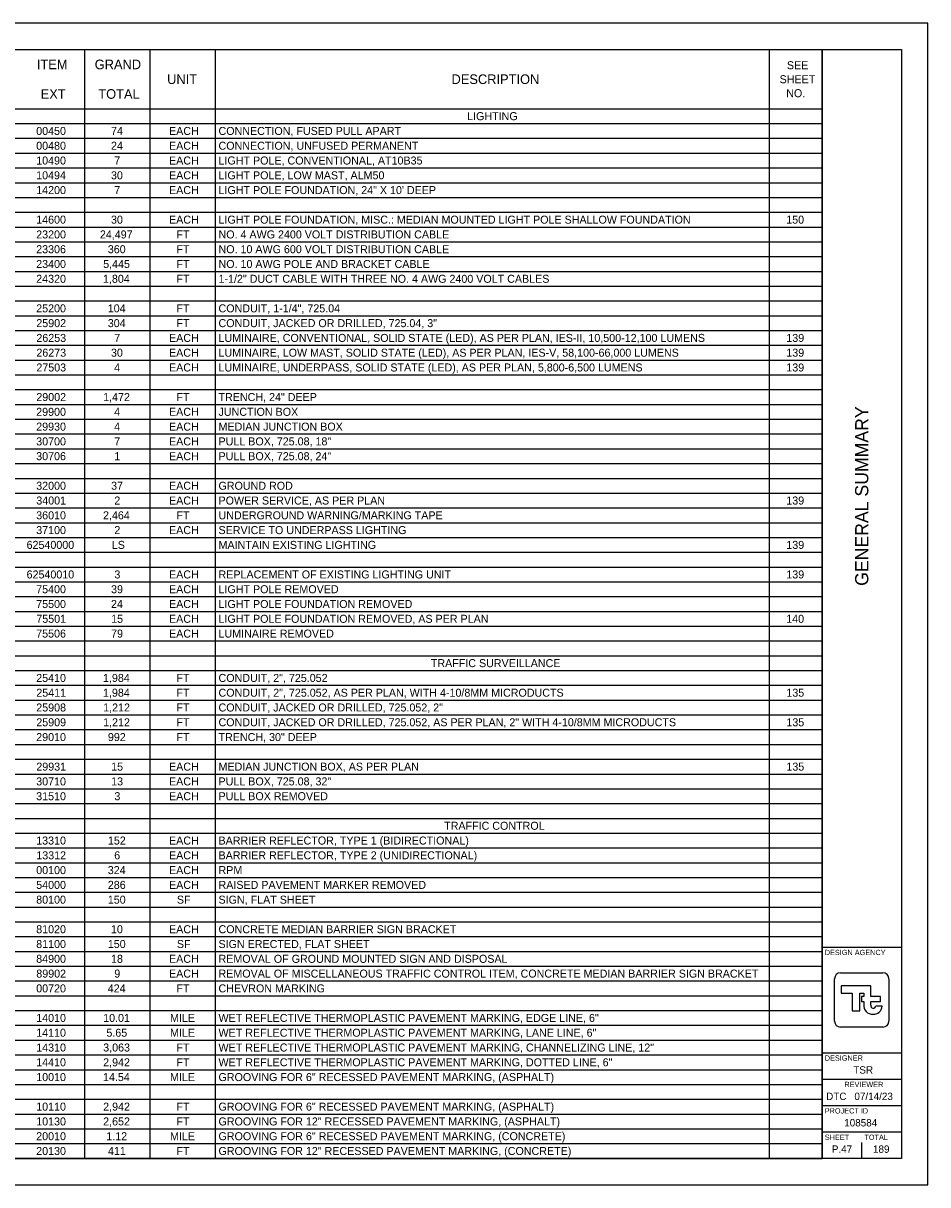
# Model space of a CAD drawing. Extents: x 0 to 34, y 0 to 22.
# Drawn here: x 16.87 to 34, y 0 to 22 of the extents above; entities that cross this region are included whole.
import ezdxf

# ---------------------------------------------------------------- set-up
doc = ezdxf.new("R2010")
doc.units = 0
for name, color, linetype in [('SH_Border', 7, 'Continuous'), ('SH_Cut_Line', 7, 'Continuous'), ('SH_Data', 7, 'Continuous'), ('SH_Text', 7, 'Continuous')]:
    doc.layers.add(name, color=color, linetype=linetype)

msp = doc.modelspace()

# ---------------------------------------------------------------- linework, layer by layer
at = {"layer": 'SH_Border'}
for p, q in [((32, 0.5), (32, 21.5)), ((32, 4.5), (33.5, 4.5)), ((32, 2.5), (33.5, 2.5)), ((32, 2), (33.5, 2)), ((32, 1.5), (33.5, 1.5)), ((32, 1), (33.5, 1))]:
    msp.add_line(p, q, dxfattribs=at)
msp.add_lwpolyline([(1.5, 21.5), (33.5, 21.5), (33.5, 0.5), (1.5, 0.5)], close=True, dxfattribs=at)
at = {"layer": 'SH_Cut_Line'}
msp.add_lwpolyline([(0, 0), (34, 0), (34, 22), (0, 22)], close=True, dxfattribs=at)
at = {"layer": 'SH_Data'}
for p, q in [((32.75, 3.5), (32.75, 3.5)), ((32.791, 3.415), (32.791, 3.415)), ((33.136, 3.385), (33.015, 3.385)), ((32.375, 0.675), (32.375, 0.675)), ((32.75, 0.5), (32.75, 0.8))]:
    msp.add_line(p, q, dxfattribs=at)
for points in [[(32.348, 4.014), (33.152, 4.014)], [(32.236, 3.099), (32.236, 3.901)], [(32.922, 3.399), (32.922, 3.47), (33.107, 3.47), (33.107, 3.568), (32.922, 3.568), (32.922, 3.768), (32.361, 3.768), (32.361, 3.632), (32.566, 3.632), (32.566, 3.294), (32.715, 3.294), (32.715, 3.63), (32.79, 3.63), (32.79, 3.568), (32.748, 3.568), (32.748, 3.47), (32.79, 3.47), (32.79, 3.415), (32.791, 3.415)], [(33.264, 3.901), (33.264, 3.099)], [(33.152, 2.986), (32.348, 2.986)]]:
    msp.add_lwpolyline(points, dxfattribs=at)
for centre, radius, start, end in [((32.348, 3.901), 0.113, 90, 180), ((33.152, 3.901), 0.113, 360, 90), ((32.949, 3.392), 0.16, 171.8856, 274.8323), ((32.968, 3.392), 0.0473, 171.8856, 350.9243), ((32.976, 3.392), 0.16, 265.1677, 357.3201), ((32.348, 3.099), 0.113, 180, 270), ((33.152, 3.099), 0.113, 270, 360)]:
    msp.add_arc(centre, radius, start, end, dxfattribs=at)
at = {"layer": 'SH_Text'}
for p, q in [((1.5, 21.5), (32, 21.5)), ((18.035, 21.5), (18.035, 0.5)), ((19.27, 21.5), (19.27, 0.5)), ((20.505, 21.5), (20.505, 0.5)), ((30.995, 21.5), (30.995, 0.5)), ((32, 21.5), (32, 0.5)), ((1.5, 20.38), (32, 20.38)), ((1.5, 20.1), (32, 20.1)), ((1.5, 19.82), (32, 19.82)), ((1.5, 19.54), (32, 19.54)), ((1.5, 19.26), (32, 19.26)), ((1.5, 18.98), (32, 18.98)), ((1.5, 18.7), (32, 18.7)), ((1.5, 18.42), (32, 18.42)), ((1.5, 18.14), (32, 18.14)), ((1.5, 17.86), (32, 17.86)), ((1.5, 17.58), (32, 17.58)), ((1.5, 17.3), (32, 17.3)), ((1.5, 17.02), (32, 17.02)), ((1.5, 16.74), (32, 16.74)), ((1.5, 16.46), (32, 16.46)), ((1.5, 16.18), (32, 16.18)), ((1.5, 15.9), (32, 15.9)), ((1.5, 15.62), (32, 15.62)), ((1.5, 15.34), (32, 15.34)), ((1.5, 15.06), (32, 15.06)), ((1.5, 14.78), (32, 14.78)), ((1.5, 14.5), (32, 14.5)), ((1.5, 14.22), (32, 14.22)), ((1.5, 13.94), (32, 13.94)), ((1.5, 13.66), (32, 13.66)), ((1.5, 13.38), (32, 13.38)), ((1.5, 13.1), (32, 13.1)), ((1.5, 12.82), (32, 12.82)), ((1.5, 12.54), (32, 12.54)), ((1.5, 12.26), (32, 12.26)), ((1.5, 11.98), (32, 11.98)), ((1.5, 11.7), (32, 11.7)), ((1.5, 11.42), (32, 11.42)), ((1.5, 11.14), (32, 11.14)), ((1.5, 10.86), (32, 10.86)), ((1.5, 10.58), (32, 10.58)), ((1.5, 10.3), (32, 10.3)), ((1.5, 10.02), (32, 10.02)), ((1.5, 9.74), (32, 9.74)), ((1.5, 9.46), (32, 9.46)), ((1.5, 9.18), (32, 9.18)), ((1.5, 8.9), (32, 8.9)), ((1.5, 8.62), (32, 8.62)), ((1.5, 8.34), (32, 8.34)), ((1.5, 8.06), (32, 8.06)), ((1.5, 7.78), (32, 7.78)), ((1.5, 7.5), (32, 7.5)), ((1.5, 7.22), (32, 7.22)), ((1.5, 6.94), (32, 6.94)), ((1.5, 6.66), (32, 6.66)), ((1.5, 6.38), (32, 6.38)), ((1.5, 6.1), (32, 6.1)), ((1.5, 5.82), (32, 5.82)), ((1.5, 5.54), (32, 5.54)), ((1.5, 5.26), (32, 5.26)), ((1.5, 4.98), (32, 4.98)), ((1.5, 4.7), (32, 4.7)), ((1.5, 4.42), (32, 4.42)), ((1.5, 4.14), (32, 4.14)), ((1.5, 3.86), (32, 3.86)), ((1.5, 3.58), (32, 3.58)), ((1.5, 3.3), (32, 3.3)), ((1.5, 3.02), (32, 3.02)), ((1.5, 2.74), (32, 2.74)), ((1.5, 2.46), (32, 2.46)), ((1.5, 2.18), (32, 2.18)), ((1.5, 1.9), (32, 1.9)), ((1.5, 1.62), (32, 1.62)), ((1.5, 1.34), (32, 1.34)), ((1.5, 1.06), (32, 1.06)), ((1.5, 0.78), (32, 0.78)), ((1.5, 0.5), (32, 0.5))]:
    msp.add_line(p, q, dxfattribs=at)

# ---------------------------------------------------------------- texts
at = {"layer": 'SH_Data'}
msp.add_text('GENERAL SUMMARY', height=0.25, rotation=90, dxfattribs=at).set_placement((32.875, 11.344))
for s, height, p in [('DESIGN AGENCY', 0.1, (32.05, 4.35)), ('DESIGNER', 0.1, (32.05, 2.35)), ('TSR', 0.14, (32.59, 2.105)), ('REVIEWER', 0.1, (32.422, 1.85)), ('DTC', 0.14, (32.076, 1.605)), ('07/14/23', 0.14, (32.611, 1.605)), ('PROJECT ID', 0.1, (32.05, 1.35)), ('108584', 0.14, (32.418, 1.105)), ('SHEET', 0.1, (32.05, 0.85)), ('TOTAL', 0.1, (32.8, 0.85)), ('P.47', 0.14, (32.183, 0.605)), ('189', 0.14, (32.963, 0.605))]:
    msp.add_text(s, height=height, dxfattribs=at).set_placement(p)
at = {"layer": 'SH_Text'}
for s, height, p in [('ITEM', 0.1818, (17.131, 21.129)), ('GRAND', 0.1818, (18.227, 21.129)), ('SEE ', 0.1515, (31.333, 21.129)), ('UNIT', 0.1818, (19.598, 20.849)), ('DESCRIPTION', 0.18184, (24.983, 20.849)), ('SHEET ', 0.1515, (31.195, 20.864)), ('EXT', 0.1818, (17.204, 20.569)), ('TOTAL', 0.1818, (18.295, 20.569)), ('NO.', 0.1515, (31.32, 20.599)), ('LIGHTING', 0.1515, (25.278, 20.164)), ('00450', 0.1515, (17.119, 19.884)), ('74', 0.1515, (18.535, 19.884)), ('EACH', 0.1515, (19.634, 19.884)), ('CONNECTION, FUSED PULL APART', 0.15153, (20.571, 19.884)), ('00480', 0.1515, (17.119, 19.604)), ('24', 0.1515, (18.535, 19.604)), ('EACH', 0.1515, (19.634, 19.604)), ('CONNECTION, UNFUSED PERMANENT', 0.15153, (20.571, 19.604)), ('10490', 0.1515, (17.119, 19.324)), ('7', 0.152, (18.597, 19.324)), ('EACH', 0.1515, (19.634, 19.324)), ('LIGHT POLE, CONVENTIONAL, AT10B35', 0.15153, (20.571, 19.324)), ('10494', 0.1515, (17.118, 19.044)), ('30', 0.1515, (18.535, 19.044)), ('EACH', 0.1515, (19.634, 19.044)), ('LIGHT POLE, LOW MAST, ALM50', 0.15153, (20.571, 19.044)), ('14200', 0.1515, (17.119, 18.764)), ('7', 0.152, (18.597, 18.764)), ('EACH', 0.1515, (19.634, 18.764)), ('LIGHT POLE FOUNDATION, 24" X 10\' DEEP', 0.15153, (20.571, 18.764)), ('14600', 0.1515, (17.119, 18.204)), ('30', 0.1515, (18.535, 18.204)), ('EACH', 0.1515, (19.634, 18.204)), ('LIGHT POLE FOUNDATION, MISC.: MEDIAN MOUNTED LIGHT POLE SHALLOW FOUNDATION', 0.15153, (20.571, 18.204)), ('150', 0.1515, (31.32, 18.204)), ('23200', 0.1515, (17.119, 17.924)), ('24,497', 0.1515, (18.325, 17.924)), ('FT', 0.1515, (19.775, 17.924)), ('NO. 4 AWG 2400 VOLT DISTRIBUTION CABLE', 0.15153, (20.571, 17.924)), ('23306', 0.1515, (17.119, 17.644)), ('360', 0.1515, (18.475, 17.644)), ('FT', 0.1515, (19.775, 17.644)), ('NO. 10 AWG 600 VOLT DISTRIBUTION CABLE', 0.15153, (20.571, 17.644)), ('23400', 0.1515, (17.119, 17.364)), ('5,445', 0.1515, (18.387, 17.364)), ('FT', 0.1515, (19.775, 17.364)), ('NO. 10 AWG POLE AND BRACKET CABLE', 0.15153, (20.571, 17.364)), ('24320', 0.1515, (17.119, 17.084)), ('1,804', 0.1515, (18.384, 17.084)), ('FT', 0.1515, (19.775, 17.084)), ('1-1/2" DUCT CABLE WITH THREE NO. 4 AWG 2400 VOLT CABLES', 0.15153, (20.571, 17.084)), ('25200', 0.1515, (17.119, 16.524)), ('104', 0.1515, (18.474, 16.524)), ('FT', 0.1515, (19.775, 16.524)), ('CONDUIT, 1-1/4", 725.04', 0.15153, (20.571, 16.524)), ('25902', 0.1515, (17.121, 16.244)), ('304', 0.1515, (18.474, 16.244)), ('FT', 0.1515, (19.775, 16.244)), ('CONDUIT, JACKED OR DRILLED, 725.04, 3"', 0.15153, (20.571, 16.244)), ('26253', 0.1515, (17.122, 15.964)), ('7', 0.152, (18.597, 15.964)), ('EACH', 0.1515, (19.634, 15.964)), ('LUMINAIRE, CONVENTIONAL, SOLID STATE (LED), AS PER PLAN, IES-II, 10,500-12,100 LUMENS', 0.15153, (20.571, 15.964)), ('139', 0.1515, (31.322, 15.964)), ('LUMINAIRE, LOW MAST, SOLID STATE (LED), AS PER PLAN, IES-V, 58,100-66,000 LUMENS', 0.15153, (20.571, 15.684)), ('26273', 0.1515, (17.122, 15.684)), ('30', 0.1515, (18.535, 15.684)), ('EACH', 0.1515, (19.634, 15.684)), ('139', 0.1515, (31.322, 15.684)), ('27503', 0.1515, (17.122, 15.404)), ('4', 0.152, (18.595, 15.404)), ('EACH', 0.1515, (19.634, 15.404)), ('LUMINAIRE, UNDERPASS, SOLID STATE (LED), AS PER PLAN, 5,800-6,500 LUMENS', 0.15153, (20.571, 15.404)), ('139', 0.1515, (31.322, 15.404)), ('29002', 0.1515, (17.121, 14.844)), ('1,472', 0.1515, (18.387, 14.844)), ('FT', 0.1515, (19.775, 14.844)), ('TRENCH, 24" DEEP', 0.15153, (20.571, 14.844)), ('29900', 0.1515, (17.119, 14.564)), ('4', 0.152, (18.595, 14.564)), ('EACH', 0.1515, (19.634, 14.564)), ('JUNCTION BOX', 0.15153, (20.571, 14.564)), ('29930', 0.1515, (17.119, 14.284)), ('4', 0.152, (18.595, 14.284)), ('EACH', 0.1515, (19.634, 14.284)), ('MEDIAN JUNCTION BOX', 0.15153, (20.571, 14.284)), ('30700', 0.1515, (17.119, 14.004)), ('7', 0.152, (18.597, 14.004)), ('EACH', 0.1515, (19.634, 14.004)), ('PULL BOX, 725.08, 18"', 0.15153, (20.571, 14.004)), ('30706', 0.1515, (17.119, 13.724)), ('1', 0.152, (18.598, 13.724)), ('EACH', 0.1515, (19.634, 13.724)), ('PULL BOX, 725.08, 24"', 0.15153, (20.571, 13.724)), ('32000', 0.1515, (17.119, 13.164)), ('37', 0.1515, (18.537, 13.164)), ('EACH', 0.1515, (19.634, 13.164)), ('GROUND ROD', 0.1515, (20.571, 13.164)), ('34001', 0.1515, (17.121, 12.884)), ('2', 0.152, (18.598, 12.884)), ('EACH', 0.1515, (19.634, 12.884)), ('POWER SERVICE, AS PER PLAN', 0.15153, (20.571, 12.884)), ('139', 0.1515, (31.322, 12.884)), ('UNDERGROUND WARNING/MARKING TAPE', 0.15153, (20.571, 12.604)), ('36010', 0.1515, (17.119, 12.604)), ('2,464', 0.1515, (18.384, 12.604)), ('FT', 0.1515, (19.775, 12.604)), ('37100', 0.1515, (17.119, 12.324)), ('2', 0.152, (18.598, 12.324)), ('EACH', 0.1515, (19.634, 12.324)), ('SERVICE TO UNDERPASS LIGHTING', 0.15153, (20.571, 12.324)), ('62540000', 0.1515, (16.937, 12.044)), ('LS', 0.1515, (18.551, 12.044)), ('MAINTAIN EXISTING LIGHTING', 0.15153, (20.571, 12.044)), ('139', 0.1515, (31.322, 12.044)), ('62540010', 0.1515, (16.937, 11.484)), ('3', 0.152, (18.599, 11.484)), ('EACH', 0.1515, (19.634, 11.484)), ('REPLACEMENT OF EXISTING LIGHTING UNIT', 0.15153, (20.571, 11.484)), ('139', 0.1515, (31.322, 11.484)), ('75400', 0.1515, (17.119, 11.204)), ('39', 0.1515, (18.537, 11.204)), ('EACH', 0.1515, (19.634, 11.204)), ('LIGHT POLE REMOVED', 0.15153, (20.571, 11.204)), ('75500', 0.1515, (17.119, 10.924)), ('24', 0.1515, (18.535, 10.924)), ('EACH', 0.1515, (19.634, 10.924)), ('LIGHT POLE FOUNDATION REMOVED', 0.15153, (20.571, 10.924)), ('75501', 0.1515, (17.121, 10.644)), ('15', 0.1515, (18.538, 10.644)), ('EACH', 0.1515, (19.634, 10.644)), ('LIGHT POLE FOUNDATION REMOVED, AS PER PLAN', 0.15153, (20.571, 10.644)), ('140', 0.1515, (31.32, 10.644)), ('75506', 0.1515, (17.119, 10.364)), ('79', 0.1515, (18.537, 10.364)), ('EACH', 0.1515, (19.634, 10.364)), ('LUMINAIRE REMOVED', 0.15153, (20.571, 10.364)), ('TRAFFIC SURVEILLANCE', 0.15153, (24.591, 9.804)), ('25410', 0.1515, (17.119, 9.524)), ('1,984', 0.1515, (18.384, 9.524)), ('FT', 0.1515, (19.775, 9.524)), ('CONDUIT, 2", 725.052', 0.15153, (20.571, 9.524)), ('25411', 0.1515, (17.121, 9.244)), ('1,984', 0.1515, (18.384, 9.244)), ('FT', 0.1515, (19.775, 9.244)), ('CONDUIT, 2", 725.052, AS PER PLAN, WITH 4-10/8MM MICRODUCTS', 0.15153, (20.571, 9.244)), ('135', 0.1515, (31.323, 9.244)), ('25908', 0.1515, (17.12, 8.964)), ('1,212', 0.1515, (18.387, 8.964)), ('FT', 0.1515, (19.775, 8.964)), ('CONDUIT, JACKED OR DRILLED, 725.052, 2"', 0.15153, (20.571, 8.964)), ('25909', 0.1515, (17.121, 8.684)), ('1,212', 0.1515, (18.387, 8.684)), ('FT', 0.1515, (19.775, 8.684)), ('CONDUIT, JACKED OR DRILLED, 725.052, AS PER PLAN, 2" WITH 4-10/8MM MICRODUCTS', 0.15153, (20.571, 8.684)), ('135', 0.1515, (31.323, 8.684)), ('29010', 0.1515, (17.119, 8.404)), ('992', 0.1515, (18.477, 8.404)), ('FT', 0.1515, (19.775, 8.404)), ('TRENCH, 30" DEEP', 0.15153, (20.571, 8.404)), ('29931', 0.1515, (17.121, 7.844)), ('15', 0.1515, (18.538, 7.844)), ('EACH', 0.1515, (19.634, 7.844)), ('MEDIAN JUNCTION BOX, AS PER PLAN', 0.15153, (20.571, 7.844)), ('135', 0.1515, (31.323, 7.844)), ('30710', 0.1515, (17.119, 7.564)), ('13', 0.1515, (18.538, 7.564)), ('EACH', 0.1515, (19.634, 7.564)), ('PULL BOX, 725.08, 32"', 0.15153, (20.571, 7.564)), ('31510', 0.1515, (17.119, 7.284)), ('3', 0.152, (18.599, 7.284)), ('EACH', 0.1515, (19.634, 7.284)), ('PULL BOX REMOVED', 0.15153, (20.571, 7.284)), ('TRAFFIC CONTROL', 0.15153, (24.843, 6.724)), ('BARRIER REFLECTOR, TYPE 1 (BIDIRECTIONAL)', 0.15153, (20.571, 6.444)), ('13310', 0.1515, (17.119, 6.444)), ('152', 0.1515, (18.477, 6.444)), ('EACH', 0.1515, (19.634, 6.444)), ('13312', 0.1515, (17.121, 6.164)), ('6', 0.152, (18.596, 6.164)), ('EACH', 0.1515, (19.634, 6.164)), ('BARRIER REFLECTOR, TYPE 2 (UNIDIRECTIONAL)', 0.15153, (20.571, 6.164)), ('00100', 0.1515, (17.119, 5.884)), ('324', 0.1515, (18.474, 5.884)), ('EACH', 0.1515, (19.634, 5.884)), ('RPM', 0.1515, (20.571, 5.884)), ('54000', 0.1515, (17.119, 5.604)), ('286', 0.1515, (18.475, 5.604)), ('EACH', 0.1515, (19.634, 5.604)), ('RAISED PAVEMENT MARKER REMOVED', 0.15153, (20.571, 5.604)), ('80100', 0.1515, (17.119, 5.324)), ('150', 0.1515, (18.475, 5.324)), ('SF', 0.1515, (19.783, 5.324)), ('SIGN, FLAT SHEET', 0.15153, (20.571, 5.324)), ('81020', 0.1515, (17.119, 4.764)), ('10', 0.1515, (18.535, 4.764)), ('EACH', 0.1515, (19.634, 4.764)), ('CONCRETE MEDIAN BARRIER SIGN BRACKET', 0.15153, (20.571, 4.764)), ('81100', 0.1515, (17.119, 4.484)), ('150', 0.1515, (18.475, 4.484)), ('SF', 0.1515, (19.783, 4.484)), ('SIGN ERECTED, FLAT SHEET', 0.15153, (20.571, 4.484)), ('84900', 0.1515, (17.119, 4.204)), ('18', 0.1515, (18.536, 4.204)), ('EACH', 0.1515, (19.634, 4.204)), ('REMOVAL OF GROUND MOUNTED SIGN AND DISPOSAL', 0.15153, (20.571, 4.204)), ('89902', 0.1515, (17.121, 3.924)), ('9', 0.152, (18.598, 3.924)), ('EACH', 0.1515, (19.634, 3.924)), ('REMOVAL OF MISCELLANEOUS TRAFFIC CONTROL ITEM, CONCRETE MEDIAN BARRIER SIGN BRACKET', 0.15153, (20.571, 3.924)), ('00720', 0.1515, (17.119, 3.644)), ('424', 0.1515, (18.474, 3.644)), ('FT', 0.1515, (19.775, 3.644)), ('CHEVRON MARKING', 0.15153, (20.571, 3.644)), ('14010', 0.1515, (17.119, 3.084)), ('10.01', 0.1515, (18.387, 3.084)), ('MILE', 0.1515, (19.653, 3.084)), ('WET REFLECTIVE THERMOPLASTIC PAVEMENT MARKING, EDGE LINE, 6"', 0.15153, (20.571, 3.084)), ('14110', 0.1515, (17.119, 2.804)), ('5.65', 0.1515, (18.448, 2.804)), ('MILE', 0.1515, (19.653, 2.804)), ('WET REFLECTIVE THERMOPLASTIC PAVEMENT MARKING, LANE LINE, 6"', 0.15153, (20.571, 2.804)), ('14310', 0.1515, (17.119, 2.524)), ('3,063', 0.1515, (18.388, 2.524)), ('FT', 0.1515, (19.775, 2.524)), ('WET REFLECTIVE THERMOPLASTIC PAVEMENT MARKING, CHANNELIZING LINE, 12"', 0.15153, (20.571, 2.524)), ('14410', 0.1515, (17.119, 2.244)), ('2,942', 0.1515, (18.387, 2.244)), ('FT', 0.1515, (19.775, 2.244)), ('WET REFLECTIVE THERMOPLASTIC PAVEMENT MARKING, DOTTED LINE, 6"', 0.15153, (20.571, 2.244)), ('10010', 0.1515, (17.119, 1.964)), ('14.54', 0.1515, (18.384, 1.964)), ('MILE', 0.1515, (19.653, 1.964)), ('GROOVING FOR 6" RECESSED PAVEMENT MARKING, (ASPHALT)', 0.15153, (20.571, 1.964)), ('10110', 0.1515, (17.119, 1.404)), ('2,942', 0.1515, (18.387, 1.404)), ('FT', 0.1515, (19.775, 1.404)), ('GROOVING FOR 6" RECESSED PAVEMENT MARKING, (ASPHALT)', 0.15153, (20.571, 1.404)), ('10130', 0.1515, (17.119, 1.124)), ('2,652', 0.1515, (18.387, 1.124)), ('FT', 0.1515, (19.775, 1.124)), ('GROOVING FOR 12" RECESSED PAVEMENT MARKING, (ASPHALT)', 0.15153, (20.571, 1.124)), ('20010', 0.1515, (17.119, 0.844)), ('1.12', 0.1515, (18.447, 0.844)), ('MILE', 0.1515, (19.653, 0.844)), ('GROOVING FOR 6" RECESSED PAVEMENT MARKING, (CONCRETE)', 0.15153, (20.571, 0.844)), ('20130', 0.1515, (17.119, 0.564)), ('411', 0.1515, (18.477, 0.564)), ('FT', 0.1515, (19.775, 0.564)), ('GROOVING FOR 12" RECESSED PAVEMENT MARKING, (CONCRETE)', 0.15153, (20.571, 0.564))]:
    msp.add_text(s, height=height, dxfattribs=at).set_placement(p)

doc.saveas('drawing.dxf')
